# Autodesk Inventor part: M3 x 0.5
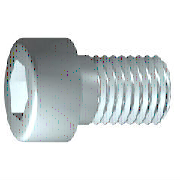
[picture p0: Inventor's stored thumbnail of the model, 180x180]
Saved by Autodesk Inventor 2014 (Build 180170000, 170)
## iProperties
IsCustomPart: 0
Created: 2015-10
Part Number: M3 x 0.5
Material: 강, 연강
Description: 6각머리 태핑 나사
Document SubType Name: Modeling
Standard: KS B 1003
Designer: mdu
Standards Organization: KS
Language: ko-KR
Size Designation: M 3 x 12
Categories: <MemberInstance><Categories><Category DisplayName="조임쇠" InternalName="e4da775c-781d-43d5-af7c-5136215cf5a6" Mnemonic="FSTN"><Category DisplayName="볼트" InternalN
Density: 1 g/cm^3
Appearance: 강철
Author: mdu
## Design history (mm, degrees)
sketch "스케치1"
  geometry: L1 (-0.867, 0)-(12, 0); L2 (12, 0)-(12, 1.5); L3 (12, 1.5)-(1.25, 1.5); L4 (1.25, 1.5)-(0.943, 1.5); L5 (0.943, 1.5)-(0, 1.5); L6 (0, 1.5)-(0, 2.75); L7 (0, 2.75)-(-3, 2.75); L8 (-3, 2.75)-(-3, 1.443); L9 (-3, 1.443)-(-1.7, 1.443); L10 (-1.7, 1.443)-(-0.867, 0); L11 (-6, 0)-(15, 0) reference; L12 (0, -0.55)-(0, 3.3) reference; L13 (1.25, 1.5)-(0, 1.5)
  constraints: 22 end point, 6 parallel, 2 collinear, 2 perpendicular, 1 horizontal, 1 point on line
  dimensions: "d1" = 10.75 distance from line of L3.end L2 (= GEL); "d2" = 0.30683 distance of L4.end L3.end (computed from GAL); "d3" = 3 distance between parallel lines of L8 L6 (= KOH); "d4" = 1.3 distance of L8.end L9.end (= INTI); "d5" = 60 deg angle of L10 L1; "d6" = 3 diameter of L3 L1 (= GD); "d7" = 3 diameter of L5 L1 (= BDM); "d8" = 2.88675 diameter of L9 L1 (= 1.1547 x SW); "d9" = 5.5 diameter of L7 L1 (= KOD); "d26" = 12 distance between parallel lines of L12 L2 (= NLG)
revolve "본체" sketch "스케치1" stored, may be unused: angle "d10" = 90 deg
sketch "스케치2"
  geometry: L1 (0, -3.85)-(0, 3.85) reference; L2 (-3.85, 0)-(3.85, 0) reference; L3 (1.443, 0)-(0.722, -1.25); L4 (0.722, -1.25)-(-0.722, -1.25); L5 (-0.722, -1.25)-(-1.443, 0); L6 (-1.443, 0)-(-0.722, 1.25); L7 (-0.722, 1.25)-(0.722, 1.25); L8 (0.722, 1.25)-(1.443, 0); 2 further points
  constraints: 12 end point, 1 coincident, 1 horizontal alignment, 1 point on line, 12 other
extrude "슬롯" join sketch "스케치2" stored distance "d11" = 10; taper "d12" = 0 deg
workplane "Work Plane1"
fillet "Fillet2" dims "d30" = 0.1 (= R)
body "Solid1"
fillet "모깎기1" dims "d17" = 0.3 (= RR)
feature "스레드" dims "d13" = 10.75 (= GEL), "d14" = 0
chamfer "모따기1" distance "d15" = 0.30673 (= -0.5 x SPD + 0.5 x GD); stored, may be unused: second distance "d16" = 0.30673 (= GUL), angle "d27" = 45 deg
other parameters: "GD" = 3 (= NND) [user parameter; used in 2 equation terms], "NLG" = 12 [user parameter; used in 1 equation term], "GEL" = 10.75 [user parameter; used in 2 equation terms], "KOD" = 5.5 [user parameter; used in 1 equation term], "KOH" = 3 [user parameter; used in 1 equation term], "INTI" = 1.3 [user parameter; used in 1 equation term], "GAL" = 0.30673 (= 0.61345 x PTC) [user parameter; used in 1 equation term], "GUL" = 0.30673 (= 0.61345 x PTC) [user parameter; used in 1 equation term], "BDM" = 3 (= NND) [user parameter; used in 1 equation term], "SW" = 2.5 [user parameter; used in 2 equation terms], "RR" = 0.3 [user parameter; used in 1 equation term], "SPD" = 2.38655 (= NND - 1.2269 x PTC) [user parameter; used in 1 equation term], "d19" = 0, "d28" = 0, "d29" = 0, "R" = 0.1 [user parameter; used in 1 equation term], "PHH" = 0.1 [user parameter], "GD1" = 2.38655 (= THREADDIA - 1.2269 x PTC) [user parameter], "THREADDIA" = 3 [user parameter; used in 1 equation term], "FAWI" = 45 deg [user parameter], "PTC" = 0.5 [user parameter; used in 5 equation terms], "NND" = 3 [user parameter; used in 3 equation terms], "TOA" = 30 deg [user parameter], "E0" = 2.8875 (= 1.155 x SW) [user parameter]
